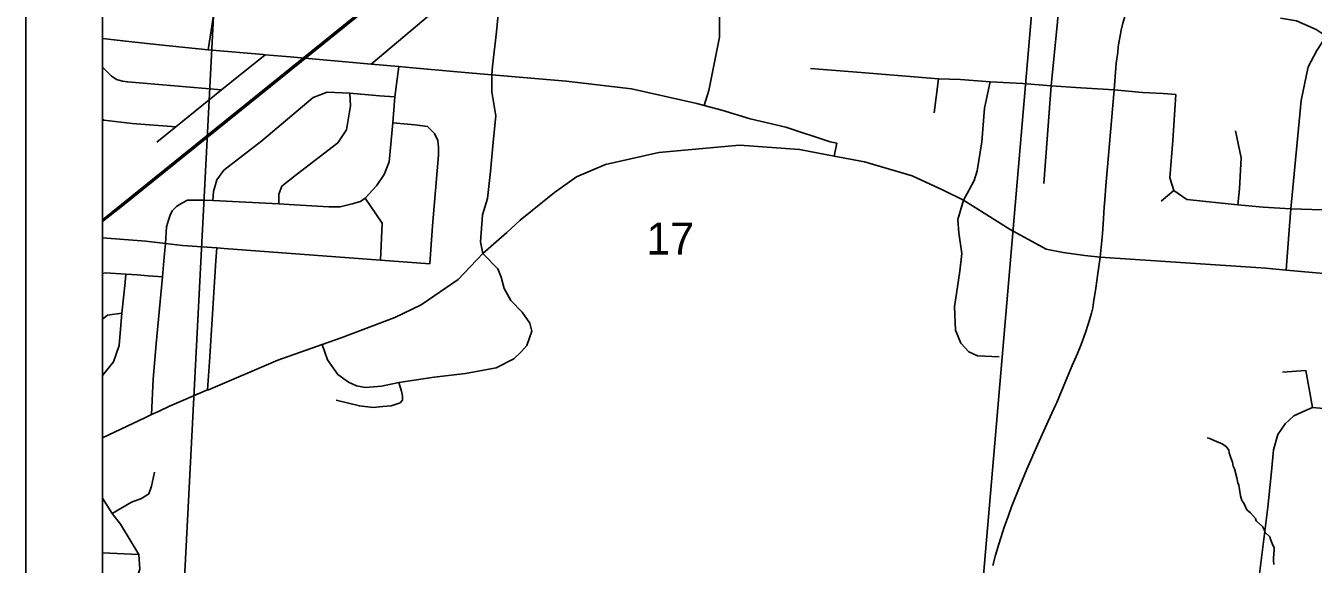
# Model space of a CAD drawing. Extents: x -7.3 to 34, y 0 to 22.
# Drawn here: x 2 to 3.68, y 15.258 to 15.96 of the extents above; entities that cross this region are included whole.
import ezdxf

# ---------------------------------------------------------------- set-up
doc = ezdxf.new("R2010")
doc.units = 0
for name, color, linetype in [('GM_X_City_Street', 7, 'Continuous'), ('GM_X_Corporation', 7, 'Continuous'), ('GM_X_County_Road', 7, 'Continuous'), ('GM_X_Minor_River', 7, 'Continuous'), ('GM_X_Rail_Line', 7, 'Continuous'), ('GM_X_Section_Text', 7, 'Continuous'), ('SH_Data', 7, 'Continuous')]:
    doc.layers.add(name, color=color, linetype=linetype)

msp = doc.modelspace()

# ---------------------------------------------------------------- linework, layer by layer
at = {"layer": 'GM_X_City_Street'}
for p, q in [((3.1854, 15.8464), (3.1912, 15.8909)), ((3.0549, 15.7902), (3.0584, 15.807)), ((3.4817, 15.7311), (3.4984, 15.745)), ((2.1, 15.2726), (2.1474, 15.2701))]:
    msp.add_line(p, q, dxfattribs=at)
for points in [[(2.451, 15.9102), (2.5692, 16.0102), (2.617, 16.0491), (2.6686, 16.0914), (2.7616, 16.1658), (2.8874, 16.2669), (2.9907, 16.354), (3.1385, 16.4741), (3.2859, 16.5922), (3.3706, 16.6616)], [(2.8852, 15.856), (2.8914, 15.8756), (2.9053, 15.9451), (2.9054, 15.9766), (2.908, 15.9932), (2.91, 16.0092), (2.9111, 16.0286), (2.9096, 16.0553), (2.9158, 16.0798), (2.9204, 16.1043), (2.9105, 16.1312), (2.8852, 16.157), (2.8784, 16.1728), (2.878, 16.1851), (2.8839, 16.2031), (2.8969, 16.2196), (2.9129, 16.2363)], [(3.3285, 15.7545), (3.3385, 15.882), (3.3464, 15.9652), (3.3525, 16.0483), (3.3559, 16.0738), (3.358, 16.1037), (3.3647, 16.1606)], [(2.2381, 15.9287), (2.2517, 16.0162), (2.2538, 16.0309), (2.2559, 16.0544), (2.2593, 16.0813), (2.2599, 16.0969), (2.2623, 16.1013)], [(2.6093, 15.9074), (2.6145, 15.9524), (2.617, 15.9798), (2.6248, 16.0016), (2.6297, 16.0138), (2.6449, 16.0483), (2.6686, 16.0914)], [(3.6375, 15.97), (3.6585, 15.9666), (3.684, 15.9555), (3.6971, 15.9464), (3.7075, 15.9375), (3.731, 15.9214), (3.7512, 15.9094), (3.7588, 15.9067), (3.8115, 15.8965), (3.8522, 15.8895), (3.8783, 15.8839), (3.9009, 15.8712), (3.9216, 15.8562), (3.9406, 15.8468), (3.9784, 15.8335), (4.0152, 15.8291), (4.0396, 15.8287), (4.0767, 15.8393), (4.1145, 15.8459), (4.1191, 15.8467), (4.1778, 15.8643), (4.1983, 15.8701)], [(3.6448, 15.6413), (3.6486, 15.6877), (3.6511, 15.7213), (3.6647, 15.8626), (3.6738, 15.9065), (3.6851, 15.928), (3.6971, 15.9464)], [(2.1, 15.9436), (2.1345, 15.9398), (2.1744, 15.9355), (2.2381, 15.9287), (2.31, 15.9225), (2.3123, 15.9223), (2.3453, 15.9195), (2.451, 15.9102), (2.4869, 15.907), (2.5053, 15.9054), (2.563, 15.9002), (2.6081, 15.8961), (2.7051, 15.888), (2.7904, 15.878), (2.8758, 15.8589), (2.8852, 15.856), (2.9086, 15.8501), (2.9456, 15.8389), (2.992, 15.8279), (3.0497, 15.8087), (3.0584, 15.807)], [(2.1711, 15.8082), (2.196, 15.8283), (2.2556, 15.8765), (2.3123, 15.9223)], [(2.1, 15.906), (2.1113, 15.8948), (2.1185, 15.8901), (2.1261, 15.888), (2.1327, 15.8868), (2.2556, 15.8765)], [(2.1643, 15.4528), (2.1664, 15.499), (2.1703, 15.5453), (2.1783, 15.6326), (2.1798, 15.648), (2.1812, 15.6628), (2.1822, 15.6761), (2.1839, 15.6978), (2.1863, 15.7066), (2.1885, 15.7128), (2.1913, 15.7187), (2.1969, 15.7244), (2.2035, 15.7288), (2.2111, 15.7325), (2.2201, 15.7324), (2.2314, 15.7327), (2.2441, 15.732), (2.3304, 15.7276), (2.3438, 15.7269), (2.3954, 15.7238), (2.4102, 15.724), (2.4259, 15.7276), (2.4368, 15.7308), (2.443, 15.735), (2.4576, 15.7515), (2.4678, 15.766), (2.4745, 15.7827), (2.479, 15.8333), (2.4817, 15.8675), (2.4869, 15.907)], [(2.5966, 15.6631), (2.5933, 15.6784), (2.5963, 15.7135), (2.6027, 15.7348), (2.6067, 15.7702), (2.6102, 15.8081), (2.6134, 15.8426), (2.6085, 15.8741), (2.6081, 15.8961), (2.6093, 15.9074)], [(3.0243, 15.9046), (3.0904, 15.8994), (3.1912, 15.8909), (3.2198, 15.89), (3.2586, 15.8872), (3.3011, 15.8848), (3.3385, 15.882), (3.3769, 15.8793), (3.4205, 15.8766), (3.4575, 15.873), (3.4844, 15.8717), (3.5012, 15.8704)], [(3.2706, 15.528), (3.2421, 15.5296), (3.2308, 15.5348), (3.2203, 15.546), (3.2135, 15.5628), (3.2122, 15.5936), (3.2192, 15.6399), (3.2215, 15.663), (3.2179, 15.69), (3.2165, 15.7075), (3.2237, 15.7326), (3.2312, 15.7459), (3.2378, 15.7583), (3.2417, 15.7708), (3.2479, 15.8089), (3.2514, 15.8526), (3.2586, 15.8872)], [(2.2441, 15.732), (2.245, 15.744), (2.2494, 15.7592), (2.2587, 15.7716), (2.3083, 15.8098), (2.3749, 15.8666), (2.3935, 15.8735), (2.423, 15.8721), (2.4616, 15.8689), (2.4817, 15.8675)], [(2.3304, 15.7276), (2.3304, 15.7405), (2.3343, 15.7507), (2.353, 15.7658), (2.4074, 15.8076), (2.4185, 15.8242), (2.4237, 15.8555), (2.423, 15.8721)], [(3.5012, 15.8704), (3.4969, 15.8105), (3.493, 15.7619), (3.4984, 15.745), (3.5152, 15.7333), (3.582, 15.7264), (3.615, 15.7233), (3.6511, 15.7213), (3.7197, 15.7193)], [(2.1, 15.8381), (2.1019, 15.8372), (2.1391, 15.8328), (2.196, 15.8283)], [(2.5274, 15.6497), (2.5309, 15.6992), (2.5369, 15.7707), (2.5385, 15.7915), (2.5388, 15.8018), (2.5378, 15.8104), (2.5333, 15.8195), (2.5243, 15.8286), (2.5077, 15.8308), (2.479, 15.8333)], [(3.582, 15.7264), (3.584, 15.7472), (3.5862, 15.7878), (3.5789, 15.8229)], [(2.4628, 15.6544), (2.4651, 15.7027), (2.443, 15.735)], [(2.1, 15.6836), (2.1568, 15.6789), (2.1822, 15.6761)], [(2.1822, 15.6761), (2.2045, 15.6733), (2.2493, 15.6704), (2.2591, 15.6697), (2.4628, 15.6544), (2.5274, 15.6497)], [(2.2373, 15.4849), (2.2397, 15.5217), (2.2481, 15.6536), (2.2493, 15.6704)], [(2.3868, 15.5442), (2.3939, 15.5242), (2.4073, 15.5051), (2.4213, 15.4951), (2.4316, 15.4903), (2.4435, 15.4881), (2.4641, 15.4899), (2.4871, 15.4947), (2.5329, 15.5016), (2.5738, 15.5064), (2.6141, 15.5139), (2.6372, 15.5255), (2.6472, 15.535), (2.654, 15.543), (2.6603, 15.5618), (2.6581, 15.5719), (2.6479, 15.5866), (2.6331, 15.6018), (2.6245, 15.6175), (2.6205, 15.632), (2.616, 15.6431), (2.5966, 15.6631)], [(2.1, 15.6368), (2.1043, 15.6379), (2.1307, 15.6361), (2.1456, 15.635), (2.1597, 15.6338), (2.1783, 15.6326)], [(2.1, 15.5037), (2.1147, 15.5217), (2.122, 15.5431), (2.1256, 15.5853), (2.1296, 15.6251), (2.1307, 15.6361)], [(2.1, 15.5772), (2.1068, 15.5824), (2.1256, 15.5853)], [(3.6792, 15.4622), (3.6708, 15.5103), (3.6401, 15.5083)], [(2.4053, 15.4714), (2.4354, 15.4641), (2.4536, 15.4622), (2.4661, 15.4632), (2.4771, 15.4644), (2.4885, 15.468), (2.4917, 15.4718), (2.4915, 15.4768), (2.4905, 15.4832), (2.4871, 15.4947)], [(3.5907, 15.0689), (3.5963, 15.1104), (3.5944, 15.1486), (3.594, 15.1868), (3.6093, 15.238), (3.6209, 15.3322), (3.6257, 15.3785), (3.6286, 15.4067), (3.6341, 15.4266), (3.6437, 15.4409), (3.6549, 15.4513), (3.6693, 15.4579), (3.6792, 15.4622), (3.7318, 15.4574), (3.7612, 15.4547), (3.7802, 15.4524)], [(2.1129, 15.3237), (2.1381, 15.3387), (2.1509, 15.3433), (2.1606, 15.3493), (2.1641, 15.3592), (2.1679, 15.3775)], [(2.1356, 15.2086), (2.1359, 15.2107), (2.1489, 15.2511), (2.1474, 15.2701), (2.1236, 15.3097), (2.1129, 15.3237), (2.1, 15.3439)]]:
    msp.add_lwpolyline(points, dxfattribs=at)
at = {"layer": 'GM_X_Corporation'}
for points in [[(2.1, 20.0921), (2.1, 14.1)], [(2.1, 17.0429), (2.1, 14.1)], [(2.1, 16.5161), (2.1, 14.1)]]:
    msp.add_lwpolyline(points, dxfattribs=at)
for points in [[(2.1, 16.2578), (2.1, 15.242), (2.2068, 15.2308), (2.2589, 16.243)], [(2.2589, 16.243), (3.3302, 16.1779), (3.2417, 15.1468), (2.2068, 15.2308)]]:
    msp.add_lwpolyline(points, close=True, dxfattribs=at)
at = {"layer": 'GM_X_County_Road'}
msp.add_line((2.1, 15.4225), (2.1562, 15.449), dxfattribs=at)
for points in [[(3.4262, 15.9355), (3.4269, 15.9402), (3.4282, 15.9472), (3.4297, 15.9546), (3.4319, 15.9636), (3.435, 15.9734), (3.4382, 15.9823), (3.4432, 15.994), (3.4471, 16.0023), (3.451, 16.0094), (3.4564, 16.0186), (3.4611, 16.026), (3.4664, 16.0336), (3.4715, 16.0401), (3.4743, 16.0437), (3.4807, 16.0511), (3.4877, 16.0586), (3.4943, 16.0648), (3.5014, 16.071)], [(3.4163, 15.8261), (3.4205, 15.8766), (3.4233, 15.911), (3.4251, 15.9259), (3.4258, 15.9326), (3.4262, 15.9355)], [(3.4079, 15.7279), (3.4101, 15.7566), (3.4133, 15.7909), (3.4158, 15.8212), (3.4163, 15.8261)], [(2.2383, 15.4853), (2.3289, 15.524), (2.3868, 15.5442), (2.4118, 15.5529), (2.4817, 15.5793), (2.5162, 15.5961), (2.5643, 15.6291), (2.5966, 15.6631), (2.6279, 15.6906), (2.6451, 15.7067), (2.69, 15.7425), (2.719, 15.763), (2.7565, 15.7793), (2.8263, 15.7946), (2.9316, 15.8044), (3.01, 15.7989), (3.0549, 15.7902), (3.0948, 15.7825), (3.157, 15.7644), (3.1972, 15.7458), (3.2237, 15.7326), (3.2846, 15.6942), (3.3317, 15.6686), (3.3538, 15.6645), (3.3824, 15.6602), (3.4023, 15.6584)], [(3.3935, 15.5989), (3.3964, 15.6177), (3.399, 15.6367), (3.4023, 15.6584), (3.4054, 15.6887), (3.4068, 15.7082), (3.4076, 15.724), (3.4079, 15.7279)], [(3.4023, 15.6584), (3.6184, 15.6439), (3.6448, 15.6413), (3.7283, 15.634), (3.7941, 15.6285), (3.8968, 15.6212), (4.0748, 15.6073), (4.1247, 15.603), (4.1525, 15.6007), (4.3155, 15.5841)], [(3.3456, 15.4687), (3.3569, 15.4959), (3.3657, 15.5167), (3.3726, 15.5324), (3.3776, 15.5444), (3.3832, 15.5597), (3.3869, 15.5721), (3.3909, 15.5851), (3.3925, 15.5922), (3.3935, 15.5989)], [(2.1562, 15.449), (2.1643, 15.4528), (2.1741, 15.4574), (2.1876, 15.4637), (2.2373, 15.4849), (2.2383, 15.4853)], [(3.2972, 15.3595), (3.3065, 15.3816), (3.321, 15.4142), (3.3344, 15.4443), (3.3445, 15.4659), (3.3456, 15.4687)], [(3.262, 15.2557), (3.2657, 15.2693), (3.2698, 15.2839), (3.2727, 15.292), (3.2771, 15.3059), (3.2821, 15.3199), (3.2867, 15.3324), (3.2972, 15.3595)]]:
    msp.add_lwpolyline(points, dxfattribs=at)
at = {"layer": 'GM_X_Minor_River'}
for points in [[(3.583, 15.3605), (3.5819, 15.3639), (3.5808, 15.3704), (3.5775, 15.3818), (3.576, 15.3856), (3.5749, 15.3909), (3.5723, 15.3978), (3.5704, 15.4031), (3.5701, 15.4062), (3.5667, 15.4111), (3.5607, 15.415), (3.5573, 15.4165), (3.5479, 15.4204), (3.5452, 15.4216), (3.5418, 15.4223)], [(3.6291, 15.2573), (3.6284, 15.2623), (3.6284, 15.2649), (3.6288, 15.2714), (3.6292, 15.2755), (3.6293, 15.2789), (3.6267, 15.2847), (3.6248, 15.2888), (3.6237, 15.2934), (3.6177, 15.2988), (3.6166, 15.3014), (3.6143, 15.3068), (3.6057, 15.314), (3.605, 15.3171), (3.5986, 15.3247), (3.5937, 15.3286), (3.5892, 15.3381), (3.587, 15.3408), (3.5855, 15.3468), (3.5844, 15.3525), (3.583, 15.3605)]]:
    msp.add_lwpolyline(points, dxfattribs=at)
at = {"layer": 'GM_X_Rail_Line'}
for points in [[(2.1, 15.707), (2.1249, 15.7268), (2.5382, 16.0605), (2.9557, 16.4006), (3.414, 16.7747), (3.4488, 16.8065), (3.4909, 16.8436), (3.5233, 16.8776), (3.548, 16.9034), (3.5722, 16.9333), (3.6345, 17.0151)], [(2.1, 15.7046), (2.1261, 15.7254), (2.5394, 16.059), (2.9569, 16.3991), (3.4153, 16.7732), (3.4501, 16.805), (3.4922, 16.8422), (3.5247, 16.8762), (3.5495, 16.9022), (3.5737, 16.9321), (3.636, 17.0139)]]:
    msp.add_lwpolyline(points, dxfattribs=at)
at = {"layer": 'SH_Data'}
for p, q in [((2, 21), (2, 14)), ((2.1, 20.9), (2.1, 14.1))]:
    msp.add_line(p, q, dxfattribs=at)

# ---------------------------------------------------------------- texts
at = {"layer": 'GM_X_Section_Text'}
msp.add_text('17', height=0.04186, rotation=0, dxfattribs=at).set_placement((2.81, 15.6615))

doc.saveas('drawing.dxf')
